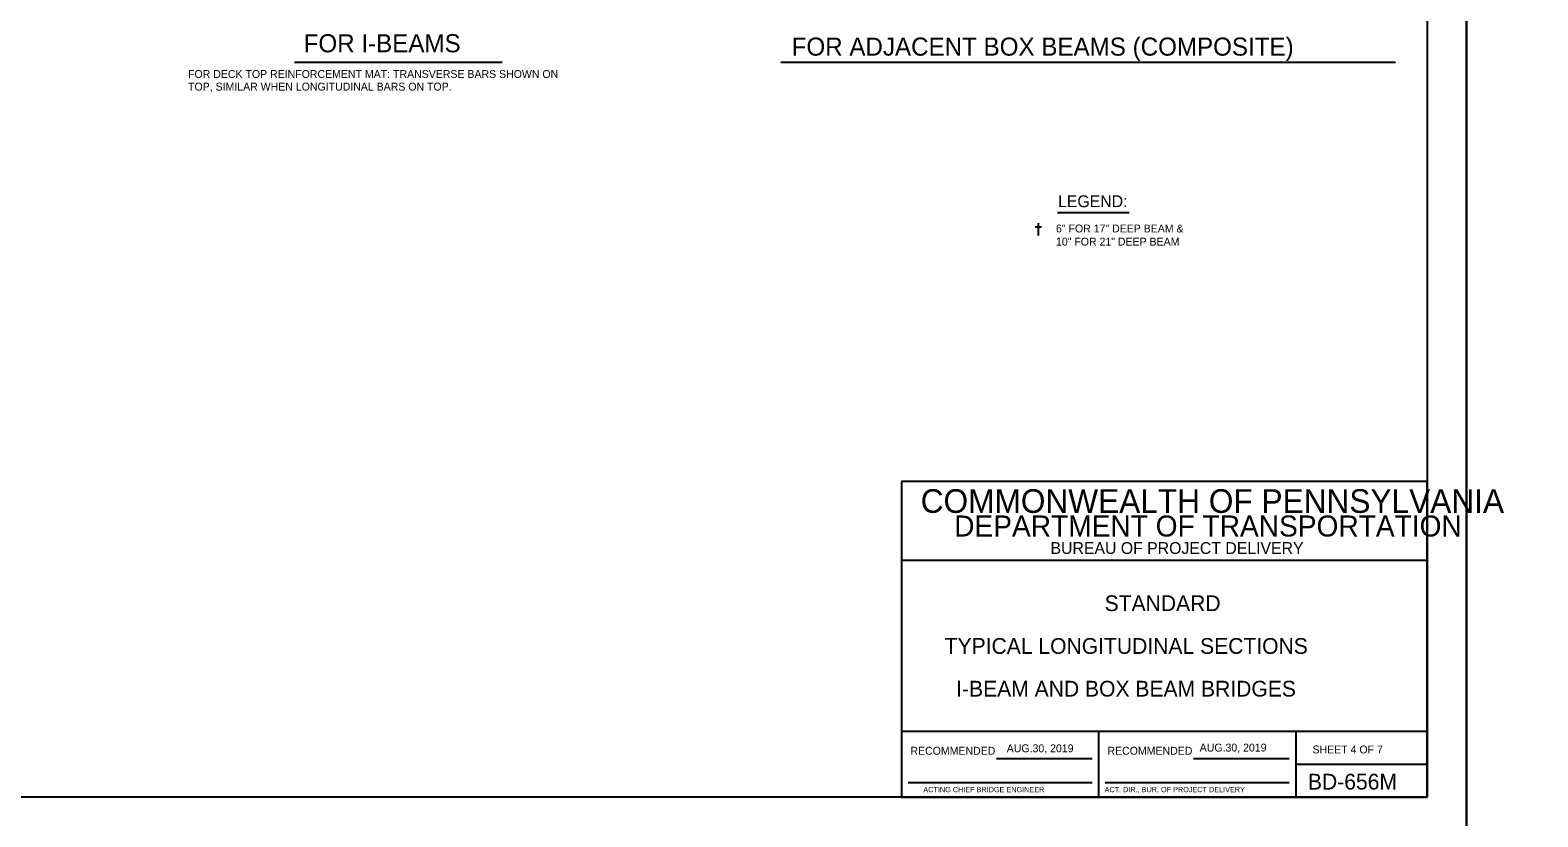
# Model space of a CAD drawing. Extents: x 638653 to 642302, y 298557 to 300414.
# Drawn here: x 639276 to 639850, y 299158 to 299457 of the extents above; entities that cross this region are included whole.
import ezdxf

# ---------------------------------------------------------------- set-up
doc = ezdxf.new("R2010")
doc.units = 0
doc.layers.add('1', color=7, linetype='Continuous')
doc.layers.add('PLT-BNDY', color=7, linetype='Continuous')

msp = doc.modelspace()

# ---------------------------------------------------------------- linework, layer by layer
at = {"layer": '1'}
for p, q in [((639808.16, 299729.52), (639808.16, 299165.52)), ((639377.04, 299445.04), (639456.17, 299445.04)), ((639562.17, 299445.04), (639796.07, 299445.04)), ((639667.47, 299387.96), (639694.76, 299387.96)), ((639659, 299382.43), (639661.42, 299382.43)), ((639660.27, 299379.2), (639660.27, 299383.83)), ((639808.16, 299285.52), (639608.16, 299285.52)), ((639608.16, 299285.52), (639608.16, 299165.52)), ((639808.16, 299285.52), (639618.1, 299285.52)), ((639808.16, 299165.52), (639808.16, 299285.52)), ((639808.16, 299255.52), (639608.16, 299255.52)), ((639808.16, 299190.52), (639608.16, 299190.52)), ((639683.16, 299165.52), (639683.16, 299190.52)), ((639758.16, 299190.52), (639758.16, 299165.52)), ((639644.25, 299180.24), (639680.66, 299180.24)), ((639719.25, 299180.24), (639755.66, 299180.24)), ((639758.16, 299178.02), (639808.16, 299178.02)), ((639610.66, 299171.02), (639680.66, 299171.02)), ((639685.66, 299171.02), (639755.66, 299171.02)), ((639808.16, 299165.52), (639022.16, 299165.52)), ((639608.16, 299165.52), (639808.16, 299165.52))]:
    msp.add_line(p, q, dxfattribs=at)
at = {"layer": 'PLT-BNDY'}
for points in [[(638982.16, 299744.52), (639823.16, 299744.52), (639823.16, 299150.52), (638982.16, 299150.52)], [(639823.16, 299744.52), (640664.16, 299744.52), (640664.16, 299150.52), (639823.16, 299150.52)]]:
    msp.add_lwpolyline(points, close=True, dxfattribs=at)

# ---------------------------------------------------------------- texts
at = {"layer": '1'}
for s, height, p in [('FOR I-BEAMS', 6.8753, (639380.58, 299448.85)), ('FOR ADJACENT BOX BEAMS (COMPOSITE)', 6.8753, (639566.3, 299447.58)), ('FOR DECK TOP REINFORCEMENT MAT: TRANSVERSE BARS SHOWN ON', 3, (639336.59, 299439.09)), ('TOP, SIMILAR WHEN LONGITUDINAL BARS ON TOP.', 3, (639336.59, 299434.29)), ('LEGEND:', 4.5, (639667.69, 299389.94)), ('6" FOR 17" DEEP BEAM &', 3, (639666.89, 299380.33)), ('10" FOR 21" DEEP BEAM', 3, (639666.89, 299375.33)), ('COMMONWEALTH OF PENNSYLVANIA', 9, (639615.41, 299273.65)), ('DEPARTMENT OF TRANSPORTATION', 8.0002, (639628.16, 299264.65)), ('BUREAU OF PROJECT DELIVERY', 4.5, (639664.82, 299258.02)), ('STANDARD', 6, (639685.41, 299236.27)), ('TYPICAL LONGITUDINAL SECTIONS', 6, (639624.53, 299220.02)), ('I-BEAM AND BOX BEAM BRIDGES', 6, (639628.91, 299203.77)), ('RECOMMENDED', 3, (639611.49, 299181.65)), ('AUG.30, 2019', 3, (639648.16, 299182.58)), ('RECOMMENDED', 3, (639686.49, 299181.65)), ('AUG.30, 2019', 3, (639721.59, 299182.86)), ('SHEET 4 OF 7', 3, (639764.53, 299182.15)), ('BD-656M', 6, (639762.78, 299168.4)), ('       ACTING CHIEF BRIDGE ENGINEER', 2.0002, (639611.05, 299167.4)), ('ACT. DIR., BUR. OF PROJECT DELIVERY', 2.0002, (639685.39, 299167.4))]:
    msp.add_text(s, height=height, dxfattribs=at).set_placement(p)

doc.saveas('drawing.dxf')
